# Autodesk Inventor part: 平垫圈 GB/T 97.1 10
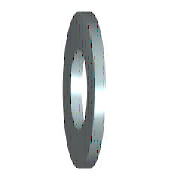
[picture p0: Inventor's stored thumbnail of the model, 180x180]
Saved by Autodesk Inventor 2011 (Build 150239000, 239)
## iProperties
Created: 2010-02
Part Number: 平垫圈 GB/T 97.1 10
Material: 低炭钢
Description: 平垫圈 - 产品等级 A
Document SubType Name: Modeling
Standard: GB/T 97.1-2002
Designer: user
Standard Revision: 2002
Standards Organization: GB
Language: zh-CN
Size Designation: 10
Categories: <MemberInstance><Categories><Category DisplayName="紧固件" InternalName="e4da775c-781d-43d5-af7c-5136215cf5a6" Mnemonic="FSTN"><Category DisplayName="垫圈" InternalN
Density: 1 g/cm^3
IsCustomPart: 1
Author: user
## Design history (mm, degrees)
body "Solid1"
sketch "Sketch"
  geometry: C1 r 10 at (0, 0); C2 r 5.25 at (0, 0); 1 further point
  constraints: 2 centre point, 2 coincident
  dimensions: "d0" = 10.5 diameter of C2 (= SD1); "d1" = 20 diameter of C1 (= SD2)
extrude "Body" new body sketch "Sketch" distance "d2" = 2 (= SD); taper "d3" = 0 deg
workaxis "Work Axis1"
workplane "Work Plane1"
other parameters: "SD1" = 10.5 [user parameter; used in 1 equation term], "SD2" = 20 [user parameter; used in 1 equation term], "SD" = 2 [user parameter; used in 1 equation term], "d4" = 0, "d5" = 0, "d6" = 0, "d7" = 0
